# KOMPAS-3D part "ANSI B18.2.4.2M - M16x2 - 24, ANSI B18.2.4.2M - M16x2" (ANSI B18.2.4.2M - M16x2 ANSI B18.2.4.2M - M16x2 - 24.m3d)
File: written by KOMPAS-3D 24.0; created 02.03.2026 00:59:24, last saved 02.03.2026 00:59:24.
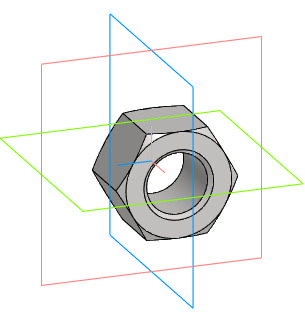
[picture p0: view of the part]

Document properties: Автор: R2D2; Полное имя файла: E:\Работа\Зайцев\GVWR3131M-2W-F-S Задвижка клиновая с выдвижным штоком DN.ru Ду50-200 Ру63\DN100\исходные материалы\ANSI B18.2.4.2M - M16x2 ANSI B18.2.4.2M - M16x2 - 24.m3d

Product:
- Body: Solid1  | qty 1
- Part/product: ANSI B18.2.4.2M - M16x2 - 24  | designation ANSI B18.2.4.2M - M16x2
    Комментарий: Типы метрических   шестигранных гаек   2
    additional columns: Сталь, мягкая

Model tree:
1. Solid1  (labels: Solid1)

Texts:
  ANSI B18.2.4.2M - M16x2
